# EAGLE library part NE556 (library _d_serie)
Dual Timer
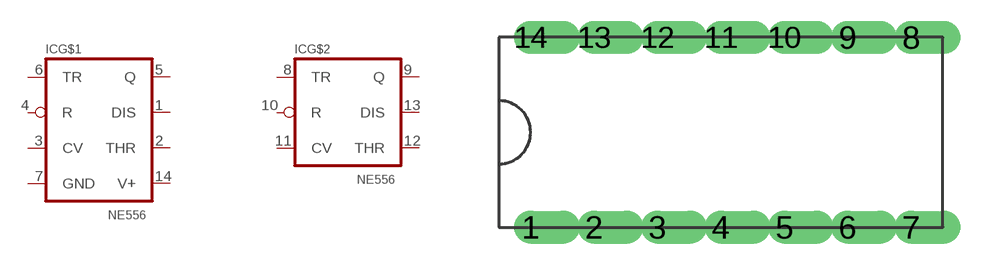
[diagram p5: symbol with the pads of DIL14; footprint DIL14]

Designator prefix IC; gates G$1=555 G$2=556

## NE556  [DIL14]
1  G$1:DIS  in
2  G$1:THR  in
3  G$1:CV  in
4  G$1:R  in
5  G$1:Q  out
6  G$1:TR  in
7  G$1:GND  pwr
8  G$2:TR  in
9  G$2:Q  out
10  G$2:R  in
11  G$2:CV  in
12  G$2:THR  in
13  G$2:DIS  in
14  G$1:V+  pwr

## Footprint DIL14 (pad centres in mm)
Dual-In-Line, 14 pins
drill 0.813 offset: 1 -7.62,-3.81; 2 -5.08,-3.81; 3 -2.54,-3.81; 4 0,-3.81; 5 2.54,-3.81; 6 5.08,-3.81; 7 7.62,-3.81; 8 7.62,3.81; 9 5.08,3.81; 10 2.54,3.81; 11 0,3.81; 12 -2.54,3.81; 13 -5.08,3.81; 14 -7.62,3.81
